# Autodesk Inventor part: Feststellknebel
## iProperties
Created: 2008-02
Part Number: Feststellknebel
Document SubType Name: Modeling
Designer: Benno
Manufacturer: Standard
Standards Organization: Custom
Author: Benno
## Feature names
1. Drehung1 [Revolution]
2. Fase1 [Chamfer]
3. Fase2 [Chamfer]
4. Fase3 [Chamfer]
